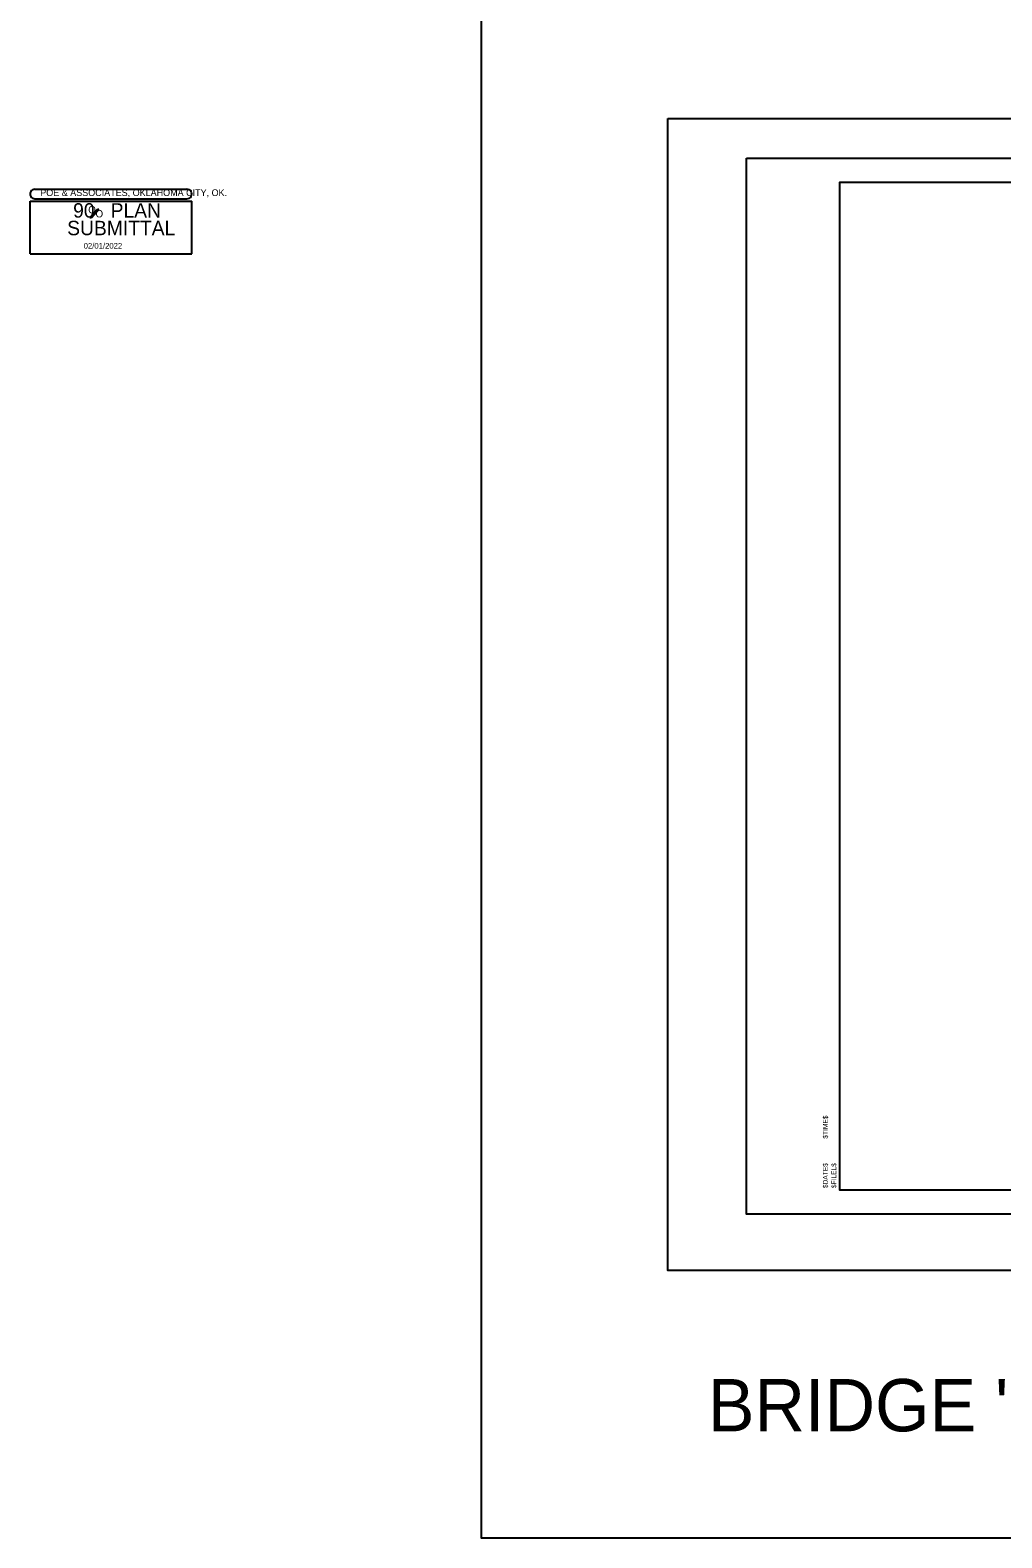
# Model space of a CAD drawing. Extents: x 12303.1 to 12355.9, y 579 to 640.5.
# Drawn here: x 12303.08 to 12323.32, y 579.03 to 610.44 of the extents above; entities that cross this region are included whole.
import ezdxf

# ---------------------------------------------------------------- set-up
doc = ezdxf.new("R2010")
doc.units = 0
for name, color, linetype in [('S', 7, 'Continuous'), ('SHT_Plot_Shape_Full', 7, 'Continuous'), ('SHT_Plot_Shape_Half', 7, 'Continuous'), ('SHT_Plot_Stamp', 7, 'Continuous'), ('SHT_Sheet_Border', 7, 'Continuous'), ('SHT_Stamp_90_Submit', 7, 'Continuous')]:
    doc.layers.add(name, color=color, linetype=linetype)

# ---------------------------------------------------------------- blocks, each defined once
blk = doc.blocks.new('Stamp_Plot_Stamp')
at = {"layer": 'SHT_Plot_Stamp'}
for s, p in [('$TIME$', (8.01, 7.43)), ('$DATE$', (8.01, 2.56)), ('$FILEL$', (8.85, 2.56))]:
    blk.add_text(s, height=0.472, rotation=90, dxfattribs=at).set_placement(p)

msp = doc.modelspace()

# ---------------------------------------------------------------- linework, layer by layer
at = {"layer": 'S'}
msp.add_lwpolyline([(12355.912, 640.488), (12312.476, 640.488), (12312.476, 579.031), (12355.912, 579.031)], close=True, dxfattribs=at)
at = {"layer": 'SHT_Plot_Shape_Full'}
msp.add_lwpolyline([(12316.36, 608.6), (12352.36, 608.6), (12352.36, 584.6), (12316.36, 584.6)], close=True, dxfattribs=at)
at = {"layer": 'SHT_Plot_Shape_Half'}
msp.add_lwpolyline([(12317.998, 607.775), (12351.998, 607.775), (12351.998, 585.775), (12317.998, 585.775)], close=True, dxfattribs=at)
at = {"layer": 'SHT_Sheet_Border'}
msp.add_lwpolyline([(12351.448, 586.275), (12319.948, 586.275), (12319.948, 607.275), (12351.448, 607.275)], close=True, dxfattribs=at)
at = {"layer": 'SHT_Stamp_90_Submit'}
for p, q in [((12303.182, 607.13), (12306.348, 607.13)), ((12303.182, 606.93), (12306.348, 606.93)), ((12303.082, 606.88), (12306.448, 606.88)), ((12303.082, 605.781), (12303.082, 606.88)), ((12304.325, 606.542), (12304.481, 606.714)), ((12304.343, 606.542), (12304.498, 606.714)), ((12304.348, 606.542), (12304.503, 606.714)), ((12304.356, 606.542), (12304.511, 606.714)), ((12304.481, 606.714), (12304.511, 606.714)), ((12306.448, 605.781), (12306.448, 606.88)), ((12304.325, 606.542), (12304.356, 606.542)), ((12303.082, 605.781), (12306.448, 605.781))]:
    msp.add_line(p, q, dxfattribs=at)
for centre, start, end in [((12303.182, 607.03), 89.9952, 270), ((12306.348, 607.03), 270, 90.0048)]:
    msp.add_arc(centre, 0.1, start, end, dxfattribs=at)

# ---------------------------------------------------------------- block references
at = {"layer": 'SHT_Plot_Stamp', "xscale": 0.21166666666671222, "yscale": 0.21166666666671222}
msp.add_blockref('Stamp_Plot_Stamp', (12317.998, 585.775), dxfattribs=at)

# ---------------------------------------------------------------- texts
at = {"layer": 'S'}
msp.add_text('BRIDGE "M" PH 2 - PQ-Notes', height=1.09025, dxfattribs=at).set_placement((12317.195, 581.25))
at = {"layer": 'SHT_Stamp_90_Submit'}
for s, height, p in [('POE & ASSOCIATES, OKLAHOMA CITY, OK.', 0.14, (12303.292, 606.987)), ('90   PLAN', 0.3, (12303.977, 606.538)), ('O', 0.153, (12304.291, 606.627)), ('O', 0.153, (12304.443, 606.542)), ('SUBMITTAL', 0.3, (12303.853, 606.171)), ('02/01/2022', 0.12, (12304.196, 605.89))]:
    msp.add_text(s, height=height, rotation=360, dxfattribs=at).set_placement(p)

doc.saveas('drawing.dxf')
